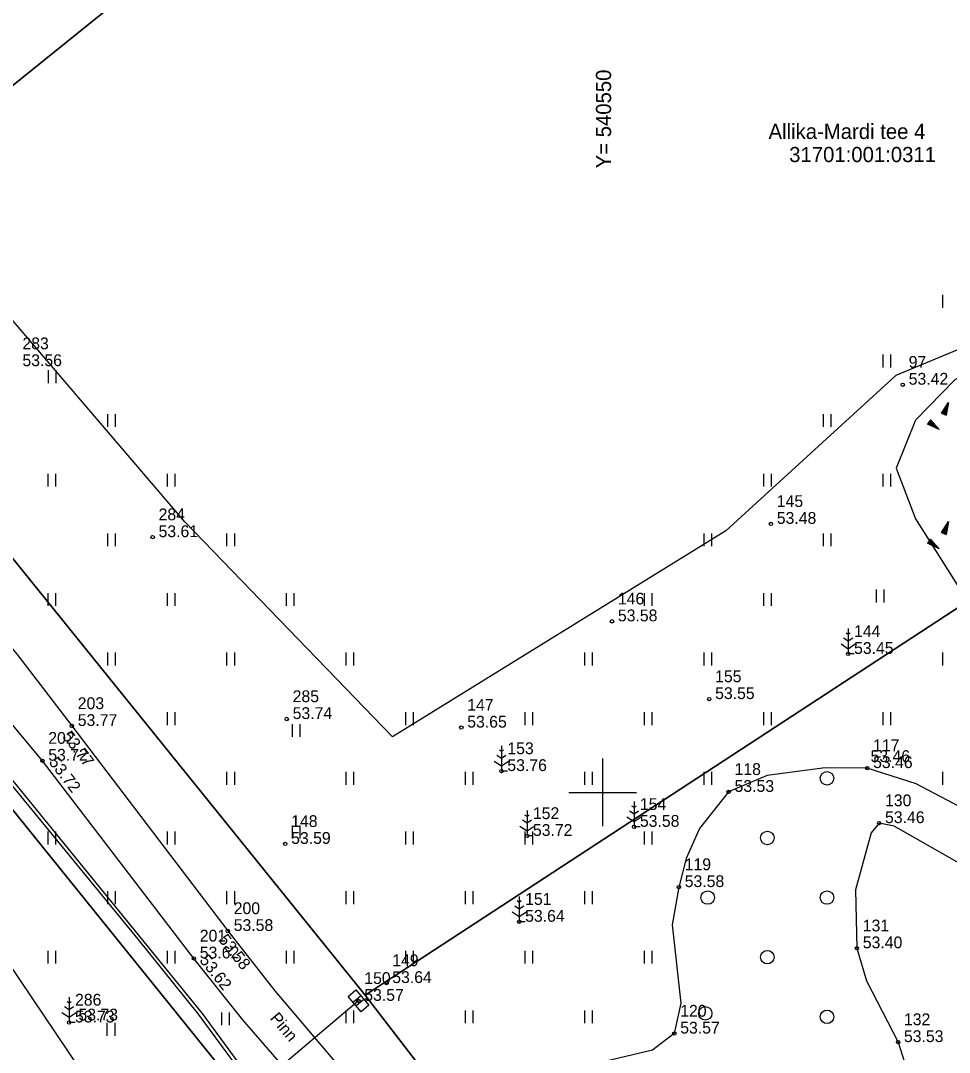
# Model space of a CAD drawing. Extents: x 538599 to 541973, y 6559689 to 6564516.
# Drawn here: x 540515.5 to 540570.5, y 6561284.6 to 6561345.8 of the extents above; entities that cross this region are included whole.
import ezdxf

# ---------------------------------------------------------------- set-up
doc = ezdxf.new("R2010")
doc.units = 0
for name, color, linetype in [('ELRAJATISMP', 7, 'Continuous'), ('HALJASTUS', 7, 'Continuous'), ('KORGUS-EH2000', 7, 'Continuous'), ('KPKAABEL', 7, 'Continuous'), ('MOOTKORG-EH2000', 7, 'Continuous'), ('MOOTMPUNKT', 7, 'Continuous'), ('MOOTNR', 7, 'Continuous'), ('MOOTPIIR', 7, 'Continuous'), ('MPKAABEL', 7, 'Continuous'), ('PIIR', 7, 'Continuous'), ('PUU', 7, 'Continuous'), ('RELJEEF', 7, 'Continuous'), ('TEE', 7, 'Continuous'), ('VORK', 7, 'Continuous')]:
    doc.layers.add(name, color=color, linetype=linetype)

msp = doc.modelspace()

# ---------------------------------------------------------------- linework, layer by layer
at = {"layer": 'ELRAJATISMP'}
for p, q in [((540535.661, 6561287.934), (540535.205, 6561287.549)), ((540535.837, 6561287.727), (540535.381, 6561287.342))]:
    msp.add_line(p, q, dxfattribs=at)
msp.add_lwpolyline([(540535.364, 6561288.287), (540536.134, 6561287.374), (540535.678, 6561286.989), (540534.908, 6561287.902)], close=True, dxfattribs=at)
at = {"layer": 'HALJASTUS'}
for p, q in [((540570.141, 6561329.498), (540570.141, 6561328.737)), ((540566.605, 6561325.962), (540566.605, 6561325.201)), ((540567.06, 6561325.962), (540567.06, 6561325.201)), ((540517.142, 6561325.031), (540517.142, 6561324.27)), ((540517.597, 6561325.031), (540517.597, 6561324.27)), ((540520.643, 6561322.427), (540520.643, 6561321.666)), ((540521.098, 6561322.427), (540521.098, 6561321.666)), ((540563.07, 6561322.427), (540563.07, 6561321.666)), ((540563.525, 6561322.427), (540563.525, 6561321.666)), ((540517.108, 6561318.891), (540517.108, 6561318.13)), ((540517.563, 6561318.891), (540517.563, 6561318.13)), ((540524.179, 6561318.891), (540524.179, 6561318.13)), ((540524.634, 6561318.891), (540524.634, 6561318.13)), ((540559.534, 6561318.891), (540559.534, 6561318.13)), ((540559.989, 6561318.891), (540559.989, 6561318.13)), ((540566.605, 6561318.891), (540566.605, 6561318.13)), ((540567.06, 6561318.891), (540567.06, 6561318.13)), ((540520.643, 6561315.356), (540520.643, 6561314.595)), ((540521.098, 6561315.356), (540521.098, 6561314.595)), ((540527.714, 6561315.356), (540527.714, 6561314.595)), ((540528.169, 6561315.356), (540528.169, 6561314.595)), ((540555.999, 6561315.356), (540555.999, 6561314.595)), ((540556.454, 6561315.356), (540556.454, 6561314.595)), ((540563.07, 6561315.356), (540563.07, 6561314.595)), ((540563.525, 6561315.356), (540563.525, 6561314.595)), ((540517.108, 6561311.82), (540517.108, 6561311.059)), ((540517.563, 6561311.82), (540517.563, 6561311.059)), ((540524.179, 6561311.82), (540524.179, 6561311.059)), ((540524.634, 6561311.82), (540524.634, 6561311.059)), ((540531.25, 6561311.82), (540531.25, 6561311.059)), ((540531.705, 6561311.82), (540531.705, 6561311.059)), ((540552.463, 6561311.82), (540552.463, 6561311.059)), ((540552.918, 6561311.82), (540552.918, 6561311.059)), ((540559.534, 6561311.82), (540559.534, 6561311.059)), ((540559.989, 6561311.82), (540559.989, 6561311.059)), ((540566.213, 6561312.024), (540566.213, 6561311.263)), ((540566.668, 6561312.024), (540566.668, 6561311.263)), ((540520.643, 6561308.285), (540520.643, 6561307.524)), ((540521.098, 6561308.285), (540521.098, 6561307.524)), ((540527.714, 6561308.285), (540527.714, 6561307.524)), ((540528.169, 6561308.285), (540528.169, 6561307.524)), ((540534.785, 6561308.285), (540534.785, 6561307.524)), ((540535.241, 6561308.285), (540535.241, 6561307.524)), ((540548.928, 6561308.285), (540548.928, 6561307.524)), ((540549.383, 6561308.285), (540549.383, 6561307.524)), ((540555.999, 6561308.285), (540555.999, 6561307.524)), ((540556.454, 6561308.285), (540556.454, 6561307.524)), ((540570.141, 6561308.285), (540570.141, 6561307.524)), ((540524.179, 6561304.749), (540524.179, 6561303.988)), ((540524.634, 6561304.749), (540524.634, 6561303.988)), ((540538.321, 6561304.749), (540538.321, 6561303.988)), ((540538.776, 6561304.749), (540538.776, 6561303.988)), ((540545.392, 6561304.749), (540545.392, 6561303.988)), ((540545.847, 6561304.749), (540545.847, 6561303.988)), ((540552.463, 6561304.749), (540552.463, 6561303.988)), ((540552.918, 6561304.749), (540552.918, 6561303.988)), ((540559.534, 6561304.749), (540559.534, 6561303.988)), ((540559.989, 6561304.749), (540559.989, 6561303.988)), ((540566.605, 6561304.749), (540566.605, 6561303.988)), ((540567.06, 6561304.749), (540567.06, 6561303.988)), ((540531.597, 6561304.045), (540531.597, 6561303.284)), ((540532.052, 6561304.045), (540532.052, 6561303.284)), ((540527.714, 6561301.214), (540527.714, 6561300.453)), ((540528.169, 6561301.214), (540528.169, 6561300.453)), ((540534.785, 6561301.214), (540534.785, 6561300.453)), ((540535.241, 6561301.214), (540535.241, 6561300.453)), ((540541.857, 6561301.214), (540541.857, 6561300.453)), ((540542.312, 6561301.214), (540542.312, 6561300.453)), ((540548.928, 6561301.214), (540548.928, 6561300.453)), ((540549.383, 6561301.214), (540549.383, 6561300.453)), ((540555.999, 6561301.214), (540555.999, 6561300.453)), ((540556.454, 6561301.214), (540556.454, 6561300.453)), ((540570.141, 6561301.214), (540570.141, 6561300.453)), ((540517.108, 6561297.678), (540517.108, 6561296.917)), ((540517.563, 6561297.678), (540517.563, 6561296.917)), ((540524.179, 6561297.678), (540524.179, 6561296.917)), ((540524.634, 6561297.678), (540524.634, 6561296.917)), ((540531.597, 6561298.026), (540531.597, 6561297.264)), ((540532.052, 6561298.026), (540532.052, 6561297.264)), ((540538.321, 6561297.678), (540538.321, 6561296.917)), ((540538.776, 6561297.678), (540538.776, 6561296.917)), ((540545.392, 6561297.678), (540545.392, 6561296.917)), ((540545.847, 6561297.678), (540545.847, 6561296.917)), ((540552.463, 6561297.678), (540552.463, 6561296.917)), ((540552.918, 6561297.678), (540552.918, 6561296.917)), ((540520.643, 6561294.143), (540520.643, 6561293.381)), ((540521.098, 6561294.143), (540521.098, 6561293.381)), ((540527.714, 6561294.143), (540527.714, 6561293.381)), ((540528.169, 6561294.143), (540528.169, 6561293.381)), ((540534.785, 6561294.143), (540534.785, 6561293.381)), ((540535.241, 6561294.143), (540535.241, 6561293.381)), ((540541.857, 6561294.143), (540541.857, 6561293.381)), ((540542.312, 6561294.143), (540542.312, 6561293.381)), ((540548.928, 6561294.143), (540548.928, 6561293.381)), ((540549.383, 6561294.143), (540549.383, 6561293.381)), ((540517.108, 6561290.607), (540517.108, 6561289.846)), ((540517.563, 6561290.607), (540517.563, 6561289.846)), ((540524.179, 6561290.607), (540524.179, 6561289.846)), ((540524.634, 6561290.607), (540524.634, 6561289.846)), ((540531.25, 6561290.607), (540531.25, 6561289.846)), ((540531.705, 6561290.607), (540531.705, 6561289.846)), ((540538.321, 6561290.607), (540538.321, 6561289.846)), ((540538.776, 6561290.607), (540538.776, 6561289.846)), ((540545.392, 6561290.607), (540545.392, 6561289.846)), ((540545.847, 6561290.607), (540545.847, 6561289.846)), ((540552.463, 6561290.607), (540552.463, 6561289.846)), ((540552.918, 6561290.607), (540552.918, 6561289.846)), ((540527.412, 6561286.952), (540527.412, 6561286.19)), ((540527.867, 6561286.952), (540527.867, 6561286.19)), ((540534.785, 6561287.072), (540534.785, 6561286.31)), ((540535.241, 6561287.072), (540535.241, 6561286.31)), ((540541.857, 6561287.072), (540541.857, 6561286.31)), ((540542.312, 6561287.072), (540542.312, 6561286.31)), ((540548.928, 6561287.072), (540548.928, 6561286.31)), ((540549.383, 6561287.072), (540549.383, 6561286.31)), ((540520.621, 6561286.33), (540520.621, 6561285.569)), ((540521.076, 6561286.33), (540521.076, 6561285.569))]:
    msp.add_line(p, q, dxfattribs=at)
for points in [[(540590.147, 6561281.335), (540590.644, 6561284.753), (540590.335, 6561287.294), (540588.959, 6561288.812), (540580.286, 6561294.676), (540574.128, 6561297.572), (540568.579, 6561300.51), (540565.68, 6561301.441), (540563.181, 6561301.459), (540559.748, 6561300.991), (540557.468, 6561300.029), (540555.748, 6561297.86), (540554.955, 6561296.084), (540554.514, 6561294.385), (540554.129, 6561292.152), (540554.626, 6561287.493), (540554.247, 6561285.697), (540552.955, 6561284.718), (540544.046, 6561282.606)], [(540570.802, 6561276.809), (540573.412, 6561275.976), (540576.87, 6561276.39), (540577.836, 6561277.043), (540578.505, 6561278.71), (540578.609, 6561282.748), (540578.298, 6561287.056), (540577.866, 6561289.9), (540576.248, 6561292.214), (540572.273, 6561295.155), (540567.268, 6561297.994), (540566.387, 6561298.177), (540565.922, 6561297.598), (540564.985, 6561294.225), (540565.068, 6561290.756), (540565.634, 6561288.817), (540567.508, 6561285.194), (540569.933, 6561277.546), (540570.802, 6561276.809)]]:
    msp.add_lwpolyline(points, dxfattribs=at)
for centre in [(540563.297, 6561300.833), (540559.762, 6561297.298), (540556.226, 6561293.762), (540563.297, 6561293.762), (540559.762, 6561290.226), (540556.08, 6561286.895), (540563.297, 6561286.691)]:
    msp.add_circle(centre, 0.4, dxfattribs=at)
at = {"layer": 'KORGUS-EH2000'}
for centre in [(540567.789, 6561324.172), (540559.971, 6561315.92), (540523.328, 6561315.133), (540550.553, 6561310.14), (540556.316, 6561305.532), (540531.276, 6561304.349), (540518.538, 6561303.936), (540541.623, 6561303.84), (540516.79, 6561301.878), (540565.68, 6561301.441), (540545.516, 6561297.416), (540531.187, 6561296.945), (540554.514, 6561294.385), (540527.782, 6561291.781), (540565.068, 6561290.756), (540525.77, 6561290.154), (540537.179, 6561288.695), (540518.376, 6561286.356), (540554.247, 6561285.697)]:
    msp.add_circle(centre, 0.1, dxfattribs=at)
at = {"layer": 'KPKAABEL'}
msp.add_lwpolyline([(540612.707, 6561251.641), (540589.754, 6561235.922), (540575.113, 6561226.32), (540574.309, 6561226.488), (540572.813, 6561227.652), (540566.988, 6561234.121), (540563.285, 6561239.03), (540553.802, 6561251.292), (540538.41, 6561271.219), (540529.488, 6561282.512), (540526.272, 6561286.879), (540510.559, 6561306.203), (540484.617, 6561338.574), (540463.547, 6561364.405), (540438.892, 6561393.697), (540425.441, 6561409.211), (540424.922, 6561409.461), (540423.725, 6561408.808), (540421.719, 6561406.34), (540419.82, 6561404.72)], dxfattribs=at)
at = {"layer": 'MOOTMPUNKT'}
for centre in [(540567.789, 6561324.172), (540559.971, 6561315.92), (540523.328, 6561315.133), (540550.553, 6561310.14), (540564.551, 6561308.209), (540556.316, 6561305.532), (540531.276, 6561304.349), (540518.538, 6561303.936), (540541.623, 6561303.84), (540516.79, 6561301.878), (540544.002, 6561301.264), (540565.68, 6561301.441), (540557.468, 6561300.029), (540551.859, 6561297.956), (540566.387, 6561298.177), (540545.516, 6561297.416), (540531.187, 6561296.945), (540554.514, 6561294.385), (540545.055, 6561292.327), (540527.782, 6561291.781), (540565.068, 6561290.756), (540525.77, 6561290.154), (540537.179, 6561288.695), (540535.521, 6561287.638), (540518.376, 6561286.356), (540554.247, 6561285.697), (540567.508, 6561285.194)]:
    msp.add_circle(centre, 0.1, dxfattribs=at)
at = {"layer": 'MOOTPIIR'}
for points in [[(540611.814, 6561347.628), (540600.551, 6561344.045), (540588.991, 6561338.307), (540579.507, 6561329.749), (540567.369, 6561324.711), (540557.296, 6561315.504), (540537.549, 6561303.29), (540525.23, 6561316.048), (540500.22, 6561345.282), (540476.488, 6561371.995), (540449.028, 6561405.277), (540428.792, 6561428.292), (540413.022, 6561448.218), (540405.096, 6561459.889), (540393.809, 6561473.145)], [(540384.887, 6561443.845), (540403.973, 6561422.469), (540424.304, 6561399.698), (540444.636, 6561376.927), (540453.177, 6561363.987), (540470.995, 6561343.689), (540492.689, 6561318.976), (540511.766, 6561294.341), (540521.974, 6561279.181), (540525.589, 6561267.954), (540536.495, 6561252.794), (540542.772, 6561231.926), (540526.603, 6561219.05), (540510.624, 6561213.468), (540498.26, 6561199.196), (540484.564, 6561192.98), (540479.618, 6561185.622), (540478.413, 6561178.328), (540490.461, 6561165.832), (540493.58, 6561162.597), (540531.105, 6561187.906), (540582.869, 6561222.817), (540621.742, 6561247.747)]]:
    msp.add_lwpolyline(points, dxfattribs=at)
at = {"layer": 'MPKAABEL'}
for points in [[(540624.746, 6561259.652), (540607.46, 6561247.735), (540595.988, 6561239.875), (540585.355, 6561232.862), (540575.156, 6561226.105), (540574.211, 6561226.297), (540572.668, 6561227.5), (540566.836, 6561233.992), (540559.418, 6561243.82), (540553.652, 6561251.158), (540543.068, 6561264.797), (540529.488, 6561282.18), (540528.898, 6561282.254), (540529.176, 6561282.594), (540526.037, 6561286.855), (540522.472, 6561291.297), (540514.38, 6561301.154), (540496.217, 6561323.662), (540475.169, 6561349.87)], [(540535.521, 6561287.638), (540529.488, 6561282.512), (540528.898, 6561282.254)]]:
    msp.add_lwpolyline(points, dxfattribs=at)
at = {"layer": 'PIIR'}
for points in [[(540491.21, 6561183.5), (540566.07, 6561233.36), (540528.84, 6561281.85), (540494.34, 6561324.62), (540458.27, 6561368.69), (540424.68, 6561408.57), (540384.55, 6561455.73), (540346.17, 6561499.11), (540330.12, 6561517.14), (540337.36, 6561523.32), (540348.28, 6561532.96), (540364.11, 6561514.94), (540353.14, 6561505.27), (540391.51, 6561461.86), (540431.74, 6561414.74), (540465.17, 6561374.89), (540501.31, 6561330.86), (540535.92, 6561287.97), (540573.77, 6561238.75), (540640.63, 6561283.66), (540646.74, 6561272.89), (540499, 6561174.36)], [(540465.17, 6561374.89), (540537.11, 6561431.06), (540569.6, 6561385.93), (540501.31, 6561330.86)], [(540501.31, 6561330.86), (540569.6, 6561385.93), (540606.26, 6561333.96), (540535.92, 6561287.97)], [(540535.92, 6561287.97), (540606.26, 6561333.96), (540640.63, 6561283.66), (540573.77, 6561238.75)], [(540422.29, 6561261.69), (540494.34, 6561324.62), (540528.84, 6561281.85), (540458.8, 6561220.37)]]:
    msp.add_lwpolyline(points, close=True, dxfattribs=at)
at = {"layer": 'PUU'}
for p, q in [((540564.551, 6561309.359), (540564.427, 6561309.442)), ((540564.551, 6561309.709), (540564.551, 6561308.209)), ((540564.675, 6561309.442), (540564.551, 6561309.359)), ((540564.127, 6561308.798), (540564.551, 6561308.516)), ((540564.551, 6561308.959), (540564.284, 6561309.137)), ((540564.818, 6561309.137), (540564.551, 6561308.959)), ((540564.551, 6561308.516), (540564.975, 6561308.798)), ((540564.911, 6561308.209), (540564.551, 6561308.209)), ((540544.002, 6561302.764), (540544.002, 6561301.264)), ((540544.002, 6561302.014), (540543.735, 6561302.192)), ((540544.002, 6561302.414), (540543.878, 6561302.497)), ((540544.126, 6561302.497), (540544.002, 6561302.414)), ((540544.269, 6561302.192), (540544.002, 6561302.014)), ((540543.578, 6561301.853), (540544.002, 6561301.571)), ((540544.002, 6561301.571), (540544.426, 6561301.853)), ((540544.362, 6561301.264), (540544.002, 6561301.264)), ((540545.516, 6561298.916), (540545.516, 6561297.416)), ((540551.859, 6561299.106), (540551.735, 6561299.189)), ((540551.859, 6561299.456), (540551.859, 6561297.956)), ((540551.983, 6561299.189), (540551.859, 6561299.106)), ((540545.516, 6561298.166), (540545.249, 6561298.344)), ((540545.516, 6561298.566), (540545.392, 6561298.649)), ((540545.64, 6561298.649), (540545.516, 6561298.566)), ((540545.783, 6561298.344), (540545.516, 6561298.166)), ((540551.435, 6561298.545), (540551.859, 6561298.263)), ((540551.859, 6561298.706), (540551.592, 6561298.884)), ((540552.126, 6561298.884), (540551.859, 6561298.706)), ((540551.859, 6561298.263), (540552.283, 6561298.545)), ((540545.092, 6561298.005), (540545.516, 6561297.723)), ((540545.516, 6561297.723), (540545.94, 6561298.005)), ((540552.219, 6561297.956), (540551.859, 6561297.956)), ((540545.876, 6561297.416), (540545.516, 6561297.416)), ((540545.055, 6561293.477), (540544.931, 6561293.56)), ((540545.055, 6561293.827), (540545.055, 6561292.327)), ((540545.179, 6561293.56), (540545.055, 6561293.477)), ((540544.631, 6561292.916), (540545.055, 6561292.634)), ((540545.055, 6561293.077), (540544.788, 6561293.255)), ((540545.322, 6561293.255), (540545.055, 6561293.077)), ((540545.055, 6561292.634), (540545.479, 6561292.916)), ((540545.415, 6561292.327), (540545.055, 6561292.327)), ((540518.376, 6561287.106), (540518.109, 6561287.284)), ((540518.376, 6561287.506), (540518.252, 6561287.589)), ((540518.376, 6561287.856), (540518.376, 6561286.356)), ((540518.5, 6561287.589), (540518.376, 6561287.506)), ((540518.643, 6561287.284), (540518.376, 6561287.106)), ((540517.952, 6561286.945), (540518.376, 6561286.663)), ((540518.376, 6561286.663), (540518.8, 6561286.945)), ((540518.736, 6561286.356), (540518.376, 6561286.356))]:
    msp.add_line(p, q, dxfattribs=at)
at = {"layer": 'RELJEEF'}
for p, q in [((540570.082, 6561322.482), (540570.502, 6561323.122)), ((540570.232, 6561322.707), (540570.357, 6561322.762)), ((540570.282, 6561322.782), (540570.452, 6561322.857)), ((540570.332, 6561322.857), (540570.462, 6561322.917)), ((540570.357, 6561322.762), (540570.442, 6561322.797)), ((540570.502, 6561323.122), (540570.362, 6561322.367)), ((540570.377, 6561322.932), (540570.477, 6561322.972)), ((540570.427, 6561323.007), (540570.487, 6561323.032)), ((540570.477, 6561323.082), (540570.497, 6561323.092)), ((540570.082, 6561322.482), (540570.407, 6561322.622)), ((540570.082, 6561322.482), (540570.362, 6561322.367)), ((540570.132, 6561322.557), (540570.417, 6561322.677)), ((540570.147, 6561322.457), (540570.397, 6561322.562)), ((540570.182, 6561322.632), (540570.432, 6561322.737)), ((540570.212, 6561322.427), (540570.387, 6561322.502)), ((540570.282, 6561322.402), (540570.377, 6561322.442)), ((540570.347, 6561322.377), (540570.362, 6561322.382)), ((540569.441, 6561322.081), (540569.256, 6561321.841)), ((540569.946, 6561321.511), (540569.256, 6561321.841)), ((540569.266, 6561321.856), (540569.271, 6561321.836)), ((540569.311, 6561321.911), (540569.326, 6561321.811)), ((540569.356, 6561321.971), (540569.381, 6561321.786)), ((540569.396, 6561322.026), (540569.431, 6561321.756)), ((540569.441, 6561322.081), (540569.946, 6561321.511)), ((540569.441, 6561322.081), (540569.486, 6561321.731)), ((540569.501, 6561322.016), (540569.541, 6561321.706)), ((540569.561, 6561321.946), (540569.596, 6561321.681)), ((540569.621, 6561321.881), (540569.636, 6561321.741)), ((540569.636, 6561321.741), (540569.651, 6561321.651)), ((540569.676, 6561321.811), (540569.706, 6561321.626)), ((540569.736, 6561321.746), (540569.756, 6561321.601)), ((540569.796, 6561321.676), (540569.811, 6561321.576)), ((540569.856, 6561321.611), (540569.866, 6561321.546)), ((540569.916, 6561321.541), (540569.921, 6561321.521)), ((540570.082, 6561315.411), (540570.502, 6561316.051)), ((540570.502, 6561316.051), (540570.362, 6561315.296)), ((540570.082, 6561315.411), (540570.407, 6561315.551)), ((540570.082, 6561315.411), (540570.362, 6561315.296)), ((540570.132, 6561315.486), (540570.417, 6561315.606)), ((540570.147, 6561315.386), (540570.397, 6561315.491)), ((540570.182, 6561315.561), (540570.432, 6561315.666)), ((540570.212, 6561315.356), (540570.387, 6561315.431)), ((540570.232, 6561315.636), (540570.357, 6561315.691)), ((540570.282, 6561315.711), (540570.452, 6561315.786)), ((540570.332, 6561315.786), (540570.462, 6561315.846)), ((540570.357, 6561315.691), (540570.442, 6561315.726)), ((540570.377, 6561315.861), (540570.477, 6561315.901)), ((540570.427, 6561315.936), (540570.487, 6561315.961)), ((540570.477, 6561316.011), (540570.497, 6561316.021)), ((540569.441, 6561315.01), (540569.256, 6561314.77)), ((540569.311, 6561314.84), (540569.326, 6561314.74)), ((540569.356, 6561314.9), (540569.381, 6561314.715)), ((540569.396, 6561314.955), (540569.431, 6561314.685)), ((540569.441, 6561315.01), (540569.946, 6561314.44)), ((540569.441, 6561315.01), (540569.486, 6561314.66)), ((540569.501, 6561314.945), (540569.541, 6561314.635)), ((540569.561, 6561314.875), (540569.596, 6561314.61)), ((540569.621, 6561314.81), (540569.636, 6561314.67)), ((540570.282, 6561315.331), (540570.377, 6561315.371)), ((540570.347, 6561315.306), (540570.362, 6561315.311)), ((540569.946, 6561314.44), (540569.256, 6561314.77)), ((540569.266, 6561314.785), (540569.271, 6561314.765)), ((540569.636, 6561314.67), (540569.651, 6561314.58)), ((540569.676, 6561314.74), (540569.706, 6561314.555)), ((540569.736, 6561314.675), (540569.756, 6561314.53)), ((540569.796, 6561314.605), (540569.811, 6561314.505)), ((540569.856, 6561314.54), (540569.866, 6561314.475)), ((540569.916, 6561314.47), (540569.921, 6561314.45))]:
    msp.add_line(p, q, dxfattribs=at)
msp.add_lwpolyline([(540589.422, 6561307.792), (540589.68, 6561309.123), (540589.163, 6561314.56), (540588.123, 6561318.281), (540586.874, 6561320.9), (540584.555, 6561323.82), (540581.615, 6561326.678), (540579.576, 6561326.947), (540575.031, 6561326.471), (540570.87, 6561324.462), (540568.551, 6561322.069), (540567.391, 6561319.222), (540568.551, 6561316.219), (540571.622, 6561311.338), (540573.345, 6561309.041), (540578.266, 6561303.19), (540579.463, 6561302.544), (540580.81, 6561302.787), (540585.578, 6561304.743), (540588.479, 6561306.571), (540589.422, 6561307.792)], dxfattribs=at)
at = {"layer": 'TEE'}
for points in [[(540480.237, 6561350.173), (540490.343, 6561338.333), (540499.283, 6561327.538), (540509.455, 6561315.157), (540515.302, 6561308.183), (540518.538, 6561303.936), (540527.782, 6561291.781), (540530.574, 6561288.237), (540536.213, 6561281.563), (540545.977, 6561268.786), (540548.214, 6561265.824), (540555.649, 6561256.763), (540560.731, 6561250.307), (540563.896, 6561245.79), (540566.417, 6561241.84), (540570.085, 6561235.281), (540571.311, 6561233.896), (540572.286, 6561233.082), (540574.391, 6561231.792), (540575.618, 6561231.655), (540576.368, 6561231.987), (540586.536, 6561238.83), (540599.72, 6561247.482), (540611.437, 6561255.604)], [(540551.357, 6561215.457), (540563.47, 6561223.953), (540565.768, 6561225.916), (540567.471, 6561228.123), (540568.24, 6561229.603), (540568.593, 6561231.912), (540567.955, 6561233.461), (540564.971, 6561239.313), (540561.94, 6561244.368), (540554.081, 6561254.966), (540546.908, 6561263.448), (540543.75, 6561267.549), (540534.504, 6561279.782), (540528.673, 6561286.519), (540525.77, 6561290.154), (540516.79, 6561301.878), (540507.075, 6561313.531), (540497.508, 6561325.645), (540488.154, 6561336.579), (540478.587, 6561348.431)]]:
    msp.add_lwpolyline(points, dxfattribs=at)
at = {"layer": 'VORK'}
for p, q in [((540550, 6561302), (540550, 6561298)), ((540548, 6561300), (540552, 6561300))]:
    msp.add_line(p, q, dxfattribs=at)

# ---------------------------------------------------------------- texts
at = {"layer": 'KORGUS-EH2000'}
for s, p in [('53.56', (540515.609, 6561325.271)), ('53.42', (540568.139, 6561324.172)), ('53.48', (540560.321, 6561315.92)), ('53.61', (540523.678, 6561315.133)), ('53.58', (540550.903, 6561310.14)), ('53.55', (540556.666, 6561305.532)), ('53.74', (540531.626, 6561304.349)), ('53.65', (540541.973, 6561303.84)), ('53.46', (540565.879, 6561301.799)), ('53.72', (540545.866, 6561297.416)), ('53.59', (540531.537, 6561296.945)), ('53.58', (540554.864, 6561294.385)), ('53.40', (540565.418, 6561290.756)), ('53.64', (540537.529, 6561288.695)), ('53.73', (540518.929, 6561286.474)), ('53.57', (540554.597, 6561285.697))]:
    msp.add_text(s, height=0.7, dxfattribs=at).set_placement(p)
for s, rotation, p in [('53.77', 307.25335, (540517.935, 6561303.31)), ('53.72', 307.45032, (540517.14, 6561301.777)), ('53.58', 308.23489, (540527.192, 6561291.253)), ('53.62', 308.61728, (540526.066, 6561290.03))]:
    msp.add_text(s, height=0.7, rotation=rotation, dxfattribs=at).set_placement(p)
at = {"layer": 'MOOTKORG-EH2000'}
for s, p in [('53.56', (540515.609, 6561325.271)), ('53.42', (540568.139, 6561324.172)), ('53.48', (540560.321, 6561315.92)), ('53.61', (540523.678, 6561315.133)), ('53.58', (540550.903, 6561310.14)), ('53.45', (540564.901, 6561308.209)), ('53.55', (540556.666, 6561305.532)), ('53.74', (540531.626, 6561304.349)), ('53.77', (540518.888, 6561303.936)), ('53.65', (540541.973, 6561303.84)), ('53.72', (540517.14, 6561301.878)), ('53.76', (540544.352, 6561301.264)), ('53.46', (540566.03, 6561301.441)), ('53.53', (540557.818, 6561300.029)), ('53.58', (540552.209, 6561297.956)), ('53.46', (540566.737, 6561298.177)), ('53.72', (540545.866, 6561297.416)), ('53.59', (540531.537, 6561296.945)), ('53.58', (540554.864, 6561294.385)), ('53.64', (540545.405, 6561292.327)), ('53.58', (540528.132, 6561291.781)), ('53.40', (540565.418, 6561290.756)), ('53.62', (540526.12, 6561290.154)), ('53.64', (540537.529, 6561288.695)), ('53.57', (540535.871, 6561287.638)), ('53.73', (540518.726, 6561286.356)), ('53.57', (540554.597, 6561285.697)), ('53.53', (540567.858, 6561285.194))]:
    msp.add_text(s, height=0.7, dxfattribs=at).set_placement(p)
at = {"layer": 'MOOTNR'}
for s, p in [('283', (540515.609, 6561326.271)), ('97', (540568.139, 6561325.172)), ('145', (540560.321, 6561316.92)), ('284', (540523.678, 6561316.133)), ('146', (540550.903, 6561311.14)), ('144', (540564.901, 6561309.209)), ('155', (540556.666, 6561306.532)), ('203', (540518.888, 6561304.936)), ('285', (540531.626, 6561305.349)), ('147', (540541.973, 6561304.84)), ('202', (540517.14, 6561302.878)), ('153', (540544.352, 6561302.264)), ('117', (540566.03, 6561302.441)), ('118', (540557.818, 6561301.029)), ('154', (540552.209, 6561298.956)), ('130', (540566.737, 6561299.177)), ('152', (540545.866, 6561298.416)), ('148', (540531.537, 6561297.945)), ('119', (540554.864, 6561295.385)), ('151', (540545.405, 6561293.327)), ('200', (540528.132, 6561292.781)), ('131', (540565.418, 6561291.756)), ('201', (540526.12, 6561291.154)), ('149', (540537.529, 6561289.695)), ('150', (540535.871, 6561288.638)), ('286', (540518.726, 6561287.356)), ('120', (540554.597, 6561286.697)), ('132', (540567.858, 6561286.194))]:
    msp.add_text(s, height=0.7, dxfattribs=at).set_placement(p)
at = {"layer": 'PIIR'}
for s, p in [('Allika-Mardi tee 4', (540559.832, 6561338.74)), ('31701:001:0311', (540561.057, 6561337.369))]:
    msp.add_text(s, height=0.9, rotation=360, dxfattribs=at).set_placement(p)
at = {"layer": 'TEE'}
msp.add_text('Pinn', height=0.7, rotation=310.09989, dxfattribs=at).set_placement((540530.243, 6561286.589))
at = {"layer": 'VORK'}
msp.add_text('Y= 540550', height=0.9, rotation=90, dxfattribs=at).set_placement((540550.5, 6561337))

doc.saveas('drawing.dxf')
